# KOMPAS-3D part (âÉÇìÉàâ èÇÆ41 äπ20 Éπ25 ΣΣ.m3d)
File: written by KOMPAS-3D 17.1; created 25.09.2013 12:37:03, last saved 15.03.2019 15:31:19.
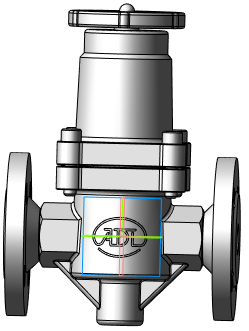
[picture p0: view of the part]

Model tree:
1. Операция без истории:4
